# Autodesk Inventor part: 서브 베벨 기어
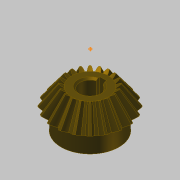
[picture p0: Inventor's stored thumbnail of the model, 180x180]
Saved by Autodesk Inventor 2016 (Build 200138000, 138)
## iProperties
Created: 2016-04
Part Number: 서브 베벨 기어
Material: 강철, 탄소
Document SubType Name: Modeling
Designer: mdu
Categories: <?xml version="1.0" encoding="UTF-16"?> <MemberInstance><Categories><FamilyTemplate><FamilyTemplateParameter ValueType="xs:double" Id="1" ObjectReferenceKey="da
Mass: 135.037 g
Surface Area: 63.6518 cm^2
Volume: 17.1585 cm^3
Density: 7.87 g/cm^3
Appearance: 얼룩무늬
CustomPartVersion: 1
Author: mdu
Revision Number: 1
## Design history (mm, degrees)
node "맨 위 점"
node "메쉬 평면2"
sketch "톱니 본체 스케치"
  geometry: L1 (0, 0)-(18.003, -31.331); L2 (18.003, -31.331)-(21.664, -28.891); L3 (21.664, -28.891)-(0, 0); L4 (20, -30)-(0, 0); L5 (10.813, -18.818)-(13.012, -17.352); L6 (18.003, -31.331)-(10.813, -18.818); L7 (21.664, -28.891)-(13.012, -17.352); L8 (0, -39.387)-(0, 6.564) reference; L9 (0, -30)-(21.664, -30)
  constraints: 16 end point, 4 point on line, 3 perpendicular, 2 collinear, 1 horizontal alignment, 1 vertical alignment
  dimensions: "d0" = 40 diameter of L4.start L8 (= da_de); "d1" = 36.00616 diameter of L1.end L8 (= da_dfe); "d2" = 43.3282 diameter of L2.end L8 (= da_dae); "d3" = 14.4 distance between parallel lines of L2 L5 (= da_b); "d4" = 28.8906 vertical distance of L2.end L1.start (= da_ve)
revolve "톱니 본체" sketch "톱니 본체 스케치" stored, may be unused: angle "d5" = 90 deg
node "시작점"
node "톱니 평면"
sketch "시작 스케치"
  geometry: L1 (0, -23.505)-(0, 10.645) reference; L2 (-0.834, -2.928)-(0.834, -2.928); A1 r 8.898 centre (-9.698, -3.713) between (-0.834, -2.928) and (-3.903, 3.04); A2 r 8.898 centre (9.698, -3.713) between (3.903, 3.04) and (0.834, -2.928); A3 r 27.357 centre (0, -24.037) between (3.903, 3.04) and (-3.903, 3.04); 1 further point
  constraints: 6 point on circle, 3 centre point, 3 symmetric about line, 2 end point, 1 coincident, 1 perpendicular, 1 other
  dimensions: "d7" = 8.89846 radius of A1 (= fd_rr); "d8" = 9.69794 horizontal distance of point (0, -24.037) A1.centre (= fd_x); "d9" = 20.32439 vertical distance of point (0, -24.037) A1.centre (= fd_y); "d57" = 27.35701 radius of A3 (= 0.5 x fd_dva + 0.3 x da_he); "d58" = 21.10901 distance from line of A3.centre L2 (= 0.5 x fd_dva - 1.12 x da_he)
node "끝점"
  node "끝 평면"
sketch "3D 스케치 오른쪽"
  node "Helical Curve Right" dims "d65" = 229.90621 (computed from da_dm, da_delta, da_beta), "d66" = 31.5, "d67" = 40 (= da_de), "d68" = -5.88003 (= -da_delta), "d69" = 12.16458 (computed from fd_loft, da_delta)
node "끝 평면 오른쪽"
sketch "끝 스케치 오른쪽"
  geometry: L1 (0, -22.649)-(0, 12.15) reference; L2 (-0.497, -1.72)-(0.497, -1.72); A1 r 5.299 centre (-5.775, -2.187) between (-0.497, -1.72) and (-2.324, 1.834); A2 r 5.299 centre (5.775, -2.187) between (2.324, 1.834) and (0.497, -1.72); A3 r 16.291 centre (0, -14.29) between (2.324, 1.834) and (-2.324, 1.834); 1 further point
  constraints: 6 point on circle, 3 centre point, 3 symmetric about line, 2 end point, 1 coincident, 1 perpendicular, 1 other
  dimensions: "d70" = 5.77526 horizontal distance of A3.centre A1.centre (computed from fd_x, fd_ratio); "d71" = 12.10346 vertical distance of point (0, -14.29) A1.centre (computed from fd_y, fd_ratio); "d72" = 5.29916 radius of A1 (computed from fd_rr, fd_ratio); "d73" = 12.57071 distance from line of point (0, -14.29) L2 (computed from d58, fd_ratio); "d74" = 16.29149 radius of A3 (computed from d57, fd_ratio)
feature "로프트 오른쪽" sketch "끝 스케치 오른쪽" dims "d75" = 0, "d77" = 0, "d79" = 0, "d80" = 90 deg, "d85" = 20, "d92" = 90 deg, "d93" = 90 deg, "da_teethtype" = 0 [user parameter]
sketch "3D 스케치 왼쪽"
  node "Helical Curve Left" dims "d26" = 229.90621 (computed from da_dm, da_delta, da_beta), "d27" = 12.16458 (computed from fd_loft, da_delta), "d28" = 40 (= da_de), "d29" = -5.88003 (= -da_delta)
node "끝 평면 왼쪽"
sketch "끝 스케치 왼쪽" dims "d56" = 10.82768 (derived)
  geometry: L1 (0, -35.087)-(0, 18.089) reference; L2 (-0.497, -1.716)-(0.497, -1.716); A1 r 5.299 centre (-5.775, -2.183) between (-0.497, -1.716) and (-2.324, 1.838); A2 r 5.299 centre (5.775, -2.183) between (2.324, 1.838) and (0.497, -1.716); A3 r 16.291 centre (0, -14.287) between (2.324, 1.838) and (-2.324, 1.838); 2 further points; 1 other entity
  constraints: 6 point on circle, 3 centre point, 3 symmetric about line, 2 end point, 1 coincident, 2 other
  dimensions: "d30" = 5.29916 radius of A1 (computed from fd_rr, fd_ratio); "d31" = 5.77526 horizontal distance of point (0, -14.287) A1.centre (computed from fd_x, fd_ratio); "d32" = 12.10346 vertical distance of A1.centre point (0, -14.287) (computed from fd_y, fd_ratio); "d61" = 16.29149 radius of A3 (computed from d57, fd_ratio); "d62" = 12.57071 distance from line of point (0, -14.287) L2 (computed from d58, fd_ratio)
feature "로프트 왼쪽" sketch "끝 스케치 왼쪽" dims "d35" = 0, "d37" = 0, "d39" = 0, "d40" = 90 deg, "d84" = 10, "d90" = 90 deg, "d91" = 90 deg, "da_teethtype" = 0 [user parameter]
sketch "본체 스케치"
  geometry: L1 (0, -35.038)-(0, -19.531) reference; L2 (18.003, -31.331)-(10.813, -18.818) reference; L3 (10.813, -18.818)-(0, -18.818); L4 (18.003, -31.331)-(0, -31.331)
  constraints: 4 end point, 2 perpendicular, 2 point on line
revolve "본체 고정" sketch "본체 스케치" stored, may be unused: angle "d46" = 90 deg
feature "피치 지름" dims angle "d47" = 90 deg
sketch "스케치8"
  geometry: C1 r 17 at (0, 0); 1 further point
  constraints: 1 centre point, 1 coincident
  dimensions: "d94" = 34 diameter of C1
extrude "돌출1" join sketch "스케치8" distance "d95" = 10; taper "d96" = 0 deg
sketch "스케치9"
  geometry: 1 further point
hole "구멍1" sketch "스케치9" at (0, 0) diameter "d97" = 12; stored, may be unused: countersink angle "d101" = 90 deg, drill point angle "d103" = 118 deg; dims "d98" = 6, "d99" = 4, "d100" = 2, "d102" = 8
sketch "스케치10"
  geometry: 1 further point
sketch "스케치11"
  geometry: 1 further point
sketch "스케치12"
  geometry: L1 (-2, 5.657)-(-2, 7.8); L2 (-2, 7.8)-(2, 7.8); L3 (2, 7.8)-(2, 5.657); A1 r 6 centre (0, 0) between (-2, 5.657) and (2, 5.657) reference; 1 further point
  constraints: 6 end point, 2 parallel, 2 point on circle, 1 perpendicular, 1 vertical
  dimensions: "d104" = 4 distance of L1.end L2.end; "d105" = 13.8 dimension on A1 L2
extrude "돌출2" cut sketch "스케치12" stored distance "d106" = 7; taper "d107" = 0 deg
chamfer "모따기1" distance "d108" = 1; stored, may be unused: second distance "d109" = 2, angle "d110" = 45 deg
body "Solid1"
feature "로프트" dims "d17" = 0, "d18" = 90 deg, "d19" = 0, "d20" = 90 deg, "d89" = 0, "da_teethtype" = 0 [user parameter]
pattern_circular "원형 패턴" dims angle "d22" = 360 deg, "d88" = 0, "da_teethtype" = 0 [user parameter]
pattern_circular "원형 패턴 오른쪽" dims angle "d82" = 360 deg, "da_teethtype" = 0 [user parameter]
pattern_circular "원형 패턴 왼쪽" dims angle "d42" = 360 deg, "da_teethtype" = 0 [user parameter]
sketch "끝 스케치"
  geometry: L1 (0, -15.359)-(0, 6.983) reference; L2 (-0.497, -1.72)-(0.497, -1.72); A1 r 5.299 centre (-5.775, -2.187) between (-0.497, -1.72) and (-2.324, 1.834); A2 r 5.299 centre (5.775, -2.187) between (2.324, 1.834) and (0.497, -1.72); A3 r 16.291 centre (0, -14.29) between (2.324, 1.834) and (-2.324, 1.834); 1 further point
  constraints: 6 point on circle, 3 centre point, 3 symmetric about line, 2 end point, 1 coincident, 1 other
  dimensions: "d12" = 5.29916 radius of A1 (computed from fd_rr, fd_ratio); "d15" = 5.77526 horizontal distance of A1.centre point (0, -14.29) (computed from fd_x, fd_ratio); "d16" = 12.10346 vertical distance of A1.centre point (0, -14.29) (computed from fd_y, fd_ratio); "d59" = 16.29149 radius of A3 (computed from d57, fd_ratio); "d60" = 12.57071 distance from line of A3.centre L2 (computed from d58, fd_ratio)
sketch "Sketch6"
  geometry: L1 (20, -30)-(0, 0) reference; L2 (0, -37.8)-(0, 6.3) reference
body "Srf1"
other parameters: "da_b" = 14.4 [user parameter; used in 2 equation terms], "da_de" = 40 [user parameter; used in 4 equation terms], "da_dae" = 43.3282 [user parameter; used in 2 equation terms], "da_dfe" = 36.00616 [user parameter; used in 1 equation term], "da_le" = 36.05551 [user parameter; used in 1 equation term], "da_omega" = 90 deg [user parameter; used in 1 equation term], "da_beta" = 0 [user parameter; used in 2 equation terms], "da_delta" = 5.88003 [user parameter; used in 8 equation terms], "da_alpha" = 20 deg [user parameter; used in 2 equation terms], "da_he" = 4.4 [user parameter; used in 4 equation terms], "da_ve" = 28.8906 [user parameter; used in 1 equation term], "fd_dv" = 48.07402 (computed from da_de, da_delta) [user parameter; used in 1 equation term], "fd_dva" = 52.07402 (computed from da_dae, da_delta) [user parameter; used in 3 equation terms], "fd_dvb" = 45.1748 (computed from fd_dv, da_alpha) [user parameter; used in 2 equation terms], "da_zv" = 240.37008 [user parameter; used in 1 equation term], "fd_loft" = 14.62 (= da_b + 0.05 x da_he) [user parameter; used in 4 equation terms], "fd_ratio" = 5.95514 (computed from da_le, fd_loft) [user parameter; used in 15 equation terms], "fd_rr" = 8.89846 (computed from fd_dd, fd_dvb) [user parameter; used in 6 equation terms], "fd_angle" = 0.66075 (computed from da_zv) [user parameter; used in 4 equation terms], "fd_x1" = 1.58709 (computed from da_dvw, fd_angle) [user parameter; used in 1 equation term], "fd_y1" = 23.98456 (computed from da_dvw, fd_angle) [user parameter; used in 1 equation term], "fd_x2" = 8.11084 (computed from fd_rr, fd_angle2, fd_angle) [user parameter; used in 1 equation term], "fd_y2" = 3.66016 (computed from fd_rr, fd_angle2, fd_angle) [user parameter; used in 1 equation term], "fd_x" = 9.69794 (= fd_x1 + fd_x2) [user parameter; used in 4 equation terms], "fd_y" = 20.32439 (= fd_y1 - fd_y2) [user parameter; used in 4 equation terms], "fd_angle2" = 3.57832 (computed from fd_dvb, fd_dd, da_alpha) [user parameter; used in 2 equation terms], "fd_dd" = 48.55402 (= fd_dva - 0.8 x da_he) [user parameter; used in 2 equation terms], "da_dvw" = 48.07402 [user parameter; used in 2 equation terms], "d11" = 14.62 (= fd_loft), "da_dm" = 32.01232 [user parameter; used in 2 equation terms], "da_x" = 0 [user parameter], "da_m" = 2 [user parameter], "d48" = 0, "d49" = 0, "d50" = 90 deg (= da_omega), "d51" = 9 deg (computed from da_z), "d52" = 0, "d53" = 0, "d54" = 0
